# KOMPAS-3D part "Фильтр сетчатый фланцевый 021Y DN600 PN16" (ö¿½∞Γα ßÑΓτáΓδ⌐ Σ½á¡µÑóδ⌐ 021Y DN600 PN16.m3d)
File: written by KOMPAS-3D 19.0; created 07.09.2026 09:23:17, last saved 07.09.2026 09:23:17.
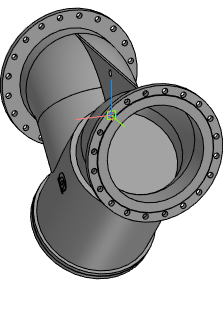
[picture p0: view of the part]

Document properties: Автор: Энергия; Полное имя файла: Z:\3.Личные\sachek\Dendor\_3D для проектировщиков\8.3 Фильтр сетчатый 021Y\021Y_STP\Фильтр сетчатый фланцевый 021Y DN600 PN16.m3d

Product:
- Part/product: Фильтр сетчатый фланцевый 021Y DN600 PN16

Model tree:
1. Операция без истории:1  (labels: Фильтр сетчатый фланцевый 021Y DN600 PN16)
